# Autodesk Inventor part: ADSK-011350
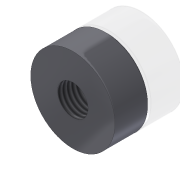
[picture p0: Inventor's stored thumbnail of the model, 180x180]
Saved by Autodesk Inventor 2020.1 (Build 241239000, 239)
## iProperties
Created: 1999-12
Part Number: ADSK-011350
Material: Pearson CD 1018
Document SubType Name: Modeling
Designer: glanglot
Density: 7.83 g/cm^3
Appearance: Metal-Steel(Polish)
Mass: 119.138 g
Surface Area: 44.3848 cm^2
Volume: 15.2155 cm^3
Control State: 0
Master: False
Checked Out: False
Shininess: 60.0
Length Units: 11269
Angle Units: 11279
Time Units: 11290
Mass Units: 11283
Length Display Precision: 3
Angle Display Precision: 2
Compacted: True
Cutlength: 1.125
Material Desc: ROUND,CD 1018,1.500 DIA
Material_Number: A084565
Dimensions: 38x38x15,5 mm
Mass: 0,119 kg
Density: 0.0
Volumn: 0.0
Area: 0.0
PropertySet Name: Model Information
Author: glanglot
Revision Number: -
Title: ADSK-011350
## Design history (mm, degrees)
node "Solide1"
  node "Extrusion4" dims "d24" = 15.5, "d25" = 0
  node "Hole2" dims "d26" = 13.835, "d27" = 9.525, "d28" = 6.35, "d29" = 60 deg, "d30" = 41.3, "d31" = 118 deg, "d35" = 32
  node "Chamfer1" dims "d32" = 0.75, "d33" = 0.75, "d34" = 45 deg
sketch "Sketch6"
  geometry: C1 r 19 at (0, 0); 1 further point
  constraints: 1 centre point, 1 coincident
  dimensions: "d23" = 38 diameter of C1
node "Corps solides"
node "Corps surfaciques"
